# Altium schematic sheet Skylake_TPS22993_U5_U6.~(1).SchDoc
size 431 x 279 mm; Date: Not shown in title block; ApprovedBy: Not shown in title block; CheckedBy: Not shown in title block; Author: Not shown in title block; CompanyName: Not shown in title block; Engineer: Not shown in title block; Organization: Not shown in title block; Address1: Not shown in title block; Address2: Not shown in title block; Address3: Not shown in title block; Address4: Not shown in title block; DocumentNumber: 1; Revision: Use project parameter SCH_Rev; SheetNumber: 3; SheetTotal: 9; PageSetup: Record=PageOptions|CenterHorizontal=True|CenterVertical=True|PrintScale=1.00|XCorrection=1.00|YCorrection=1.00|PrintKind=0|BorderSize=5000000|LeftOffset=0|BottomOffset=0|Orientation=2|PaperLength=1000|PaperWidth=1000|Scale=100|PaperSource=15|PrintQuality=600|MediaType=1|DitherType=10|PaperKind=Letter|PrintScaleMode=1
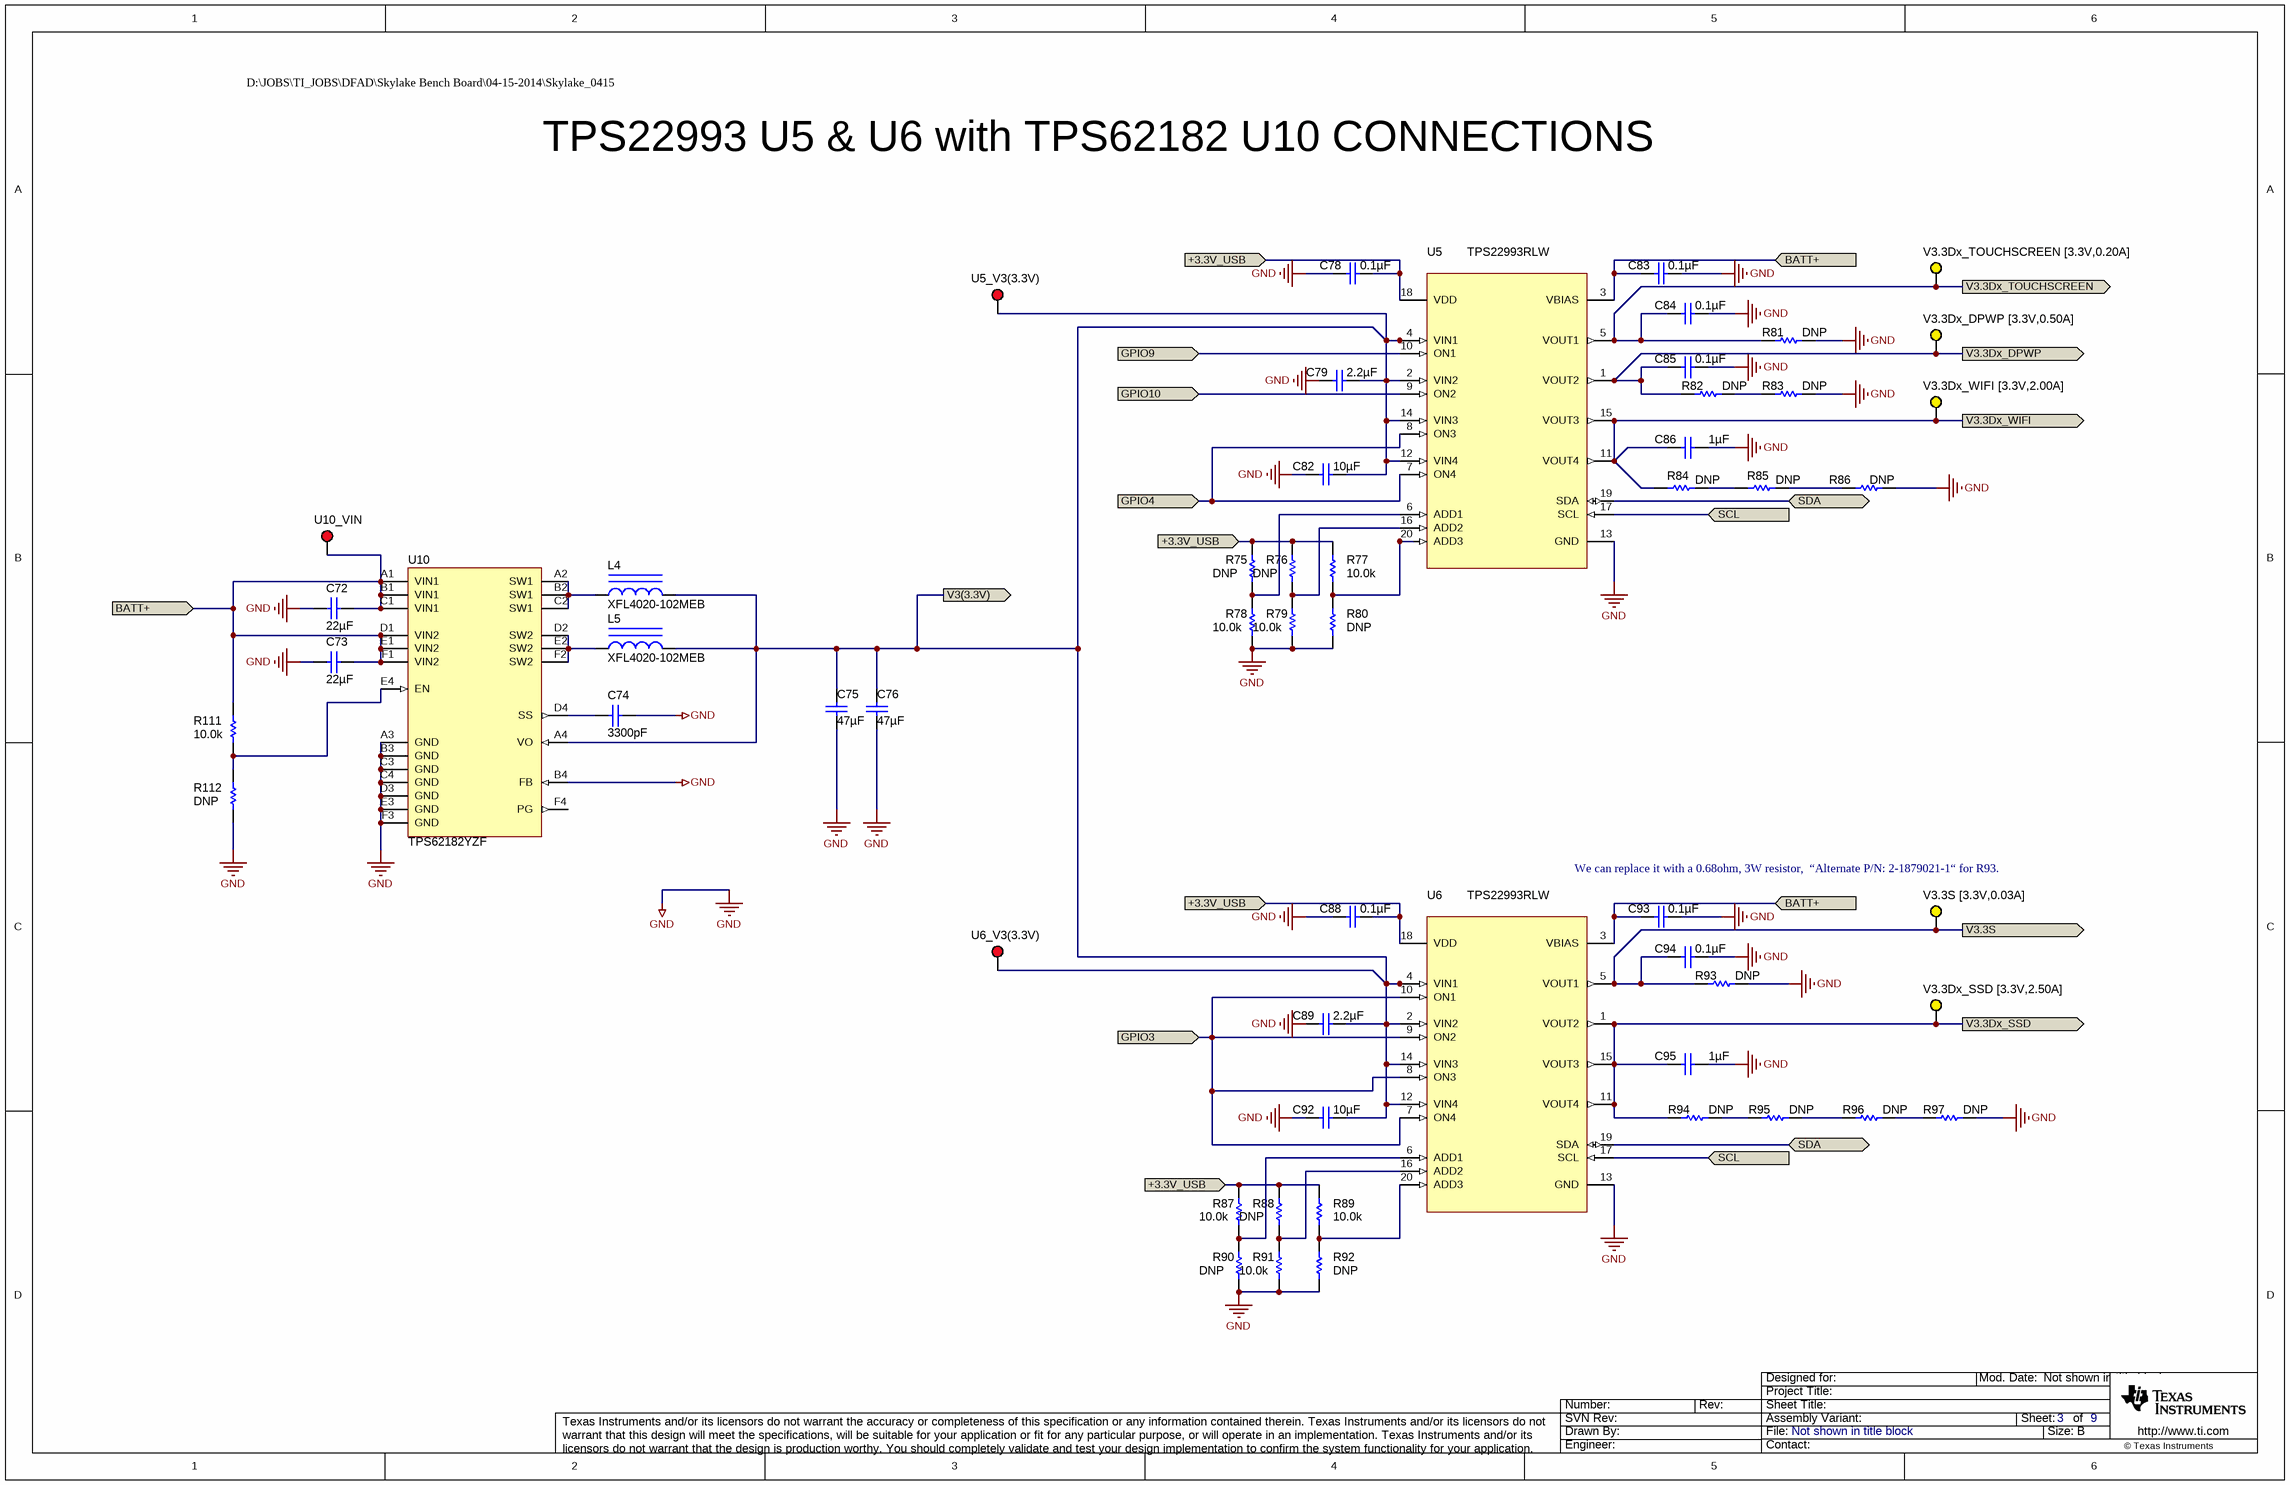
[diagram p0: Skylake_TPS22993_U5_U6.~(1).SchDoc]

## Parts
C72  ValueDisplayed: 22µF  [0805_HV]  (hidden comment: C2012JB1V226M125AC)
C73  ValueDisplayed: 22µF  [0805_HV]  (hidden comment: C2012JB1V226M125AC)
C74  ValueDisplayed: 3300pF  [0603]  (hidden comment: C0603C332J3RACTU)
C75  ValueDisplayed: 47µF  [0805_HV]  (hidden comment: C2012X5R1A476M125AC)
C76  ValueDisplayed: 47µF  [0805_HV]  (hidden comment: C2012X5R1A476M125AC)
C78  ValueDisplayed: 0.1µF  [0603]  (hidden comment: C0603C104K8RACTU)
C79  ValueDisplayed: 2.2µF  [0603]  (hidden comment: GRM188C81A225KE34D)
C82  ValueDisplayed: 10µF  [0805_HV]  (hidden comment: C2012JB1V106K085AC)
C83  ValueDisplayed: 0.1µF  [0805_HV]  (hidden comment: GMK212BJ104KGHT)
C84  ValueDisplayed: 0.1µF  [0603]  (hidden comment: C0603C104K8RACTU)
C85  ValueDisplayed: 0.1µF  [0603]  (hidden comment: C0603C104K8RACTU)
C86  ValueDisplayed: 1µF  [0603]  (hidden comment: C0603C105K8PACTU)
C88  ValueDisplayed: 0.1µF  [0603]  (hidden comment: C0603C104K8RACTU)
C89  ValueDisplayed: 2.2µF  [0603]  (hidden comment: GRM188C81A225KE34D)
C92  ValueDisplayed: 10µF  [0805_HV]  (hidden comment: C2012JB1V106K085AC)
C93  ValueDisplayed: 0.1µF  [0805_HV]  (hidden comment: GMK212BJ104KGHT)
C94  ValueDisplayed: 0.1µF  [0603]  (hidden comment: C0603C104K8RACTU)
C95  ValueDisplayed: 1µF  [0603]  (hidden comment: C0603C105K8PACTU)
L4  XFL4020-102MEB  [XFL4020]
L5  XFL4020-102MEB  [XFL4020]
R75  value DNP  [0402]  (hidden comment: CRCW040210K0FKED)
R76  value DNP  [0402]  (hidden comment: CRCW040210K0FKED)
R77  value 10.0k  [0402]  (hidden comment: CRCW040210K0FKED)
R78  value 10.0k  [0402]  (hidden comment: CRCW040210K0FKED)
R79  value 10.0k  [0402]  (hidden comment: CRCW040210K0FKED)
R80  value DNP  [0402]  (hidden comment: CRCW040210K0FKED)
R81  value DNP  [2512M]  (hidden comment: RMCF2512FT16R5)
R82  value DNP  [2512M]  (hidden comment: CRCW25123R30FKEGHP)
R83  value DNP  [2512M]  (hidden comment: CRCW25123R30FKEGHP)
R84  value DNP  [PWR5322]  (hidden comment: PWR5322WR500JE)
R85  value DNP  [PWR5322]  (hidden comment: PWR5322WR500JE)
R86  value DNP  [SM_3]  (hidden comment: 2-1879021-1)
R87  value 10.0k  [0402]  (hidden comment: CRCW040210K0FKED)
R88  value DNP  [0402]  (hidden comment: CRCW040210K0FKED)
R89  value 10.0k  [0402]  (hidden comment: CRCW040210K0FKED)
R90  value DNP  [0402]  (hidden comment: CRCW040210K0FKED)
R91  value 10.0k  [0402]  (hidden comment: CRCW040210K0FKED)
R92  value DNP  [0402]  (hidden comment: CRCW040210K0FKED)
R93  value DNP  [1206]  (hidden comment: CRCW1206110RJNEA)
R94  value DNP  [SM_3]  (hidden comment: A103634CT)
R95  value DNP  [SM_3]  (hidden comment: A103634CT)
R96  value DNP  [SM_3]  (hidden comment: A103634CT)
R97  value DNP  [SM_3]  (hidden comment: A103634CT)
R111  value 10.0k  [0402]  (hidden comment: CRCW040210K0FKED)
R112  value DNP  [0402]  (hidden comment: CRCW040210K0FKED)
U5  TPS22993RLW  [RLW0020A]
U5_V3(3.3V)  5005  [Keystone5005]  (value not drawn)
U6  TPS22993RLW  [RLW0020A]
U6_V3(3.3V)  5005  [Keystone5005]  (value not drawn)
U10  TPS62182YZF  [YZF0024AMAM]
U10_VIN  5005  [Keystone5005]  (value not drawn)
V3.3Dx_DPWP_[3.3V,0.50A]  5009  [Keystone5009]  (value not drawn)
V3.3Dx_SSD_[3.3V,2.50A]  5009  [Keystone5009]  (value not drawn)
V3.3Dx_TOUCHSCREEN_[3.3V,0.20A]  5009  [Keystone5009]  (value not drawn)
V3.3Dx_WIFI_[3.3V,2.00A]  5009  [Keystone5009]  (value not drawn)
V3.3S_[3.3V,0.03A]  5009  [Keystone5009]  (value not drawn)

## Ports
+3.3V_USB (in), BATT+ (in), GPIO3 (in), GPIO4 (in), GPIO9 (in), GPIO10 (in), SCL (in), SDA (bidir), V3(3.3V) (out), V3.3Dx_DPWP (out), V3.3Dx_SSD (out), V3.3Dx_TOUCHSCREEN (out), V3.3Dx_WIFI (out), V3.3S (out)

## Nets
GND: C72.2 C73.2 C74.1 C75.2 C76.2 C78.2 C79.2 C82.2 C83.1 C84.1 C85.1 C86.1 C88.2 C89.2 C92.2 C93.1 C94.1 C95.1 R78.1 R79.1 R80.1 R81.2 R83.2 R86.2 R90.1 R91.1 R92.1 R93.2 R97.2 R112.1 U5.13(GND) U6.13(GND) U10.A3(GND) U10.B3(GND) U10.B4(FB) U10.C3(GND) U10.C4(GND) U10.D3(GND) U10.E3(GND) U10.F3(GND)
+3.3V_USB: C78.1 C88.1 R75.2 R76.2 R77.2 R87.2 R88.2 R89.2 U5.18(VDD) U6.18(VDD) ; port +3.3V_USB
BATT+: C72.1 C73.1 C83.2 C93.2 R111.2 U5.3(VBIAS) U6.3(VBIAS) U10.A1(VIN1) U10.B1(VIN1) U10.C1(VIN1) U10.D1(VIN2) U10.E1(VIN2) U10.F1(VIN2) U10_VIN.1 ; port BATT+
GPIO3: U6.7(ON4) U6.8(ON3) U6.9(ON2) U6.10(ON1) ; port GPIO3
GPIO4: U5.7(ON4) U5.8(ON3) ; port GPIO4
GPIO9: U5.10(ON1) ; port GPIO9
GPIO10: U5.9(ON2) ; port GPIO10
SCL: U5.17(SCL) U6.17(SCL) ; port SCL
SDA: U5.19(SDA) U6.19(SDA) ; port SDA
V3(3.3V): C75.1 C76.1 C79.1 C82.1 C89.1 C92.1 L4.2 L5.2 U5.2(VIN2) U5.4(VIN1) U5.12(VIN4) U5.14(VIN3) U5_V3(3.3V).1 U6.2(VIN2) U6.4(VIN1) U6.12(VIN4) U6.14(VIN3) U6_V3(3.3V).1 U10.A4(VO) ; port V3(3.3V)
V3.3Dx_DPWP: C85.2 R82.1 U5.1(VOUT2) V3.3Dx_DPWP_[3.3V,0.50A].1 ; port V3.3Dx_DPWP
V3.3Dx_SSD: C95.2 R94.1 U6.1(VOUT2) U6.11(VOUT4) U6.15(VOUT3) V3.3Dx_SSD_[3.3V,2.50A].1 ; port V3.3Dx_SSD
V3.3Dx_TOUCHSCREEN: C84.2 R81.1 U5.5(VOUT1) V3.3Dx_TOUCHSCREEN_[3.3V,0.20A].1 ; port V3.3Dx_TOUCHSCREEN
V3.3Dx_WIFI: C86.2 R84.1 U5.11(VOUT4) U5.15(VOUT3) V3.3Dx_WIFI_[3.3V,2.00A].1 ; port V3.3Dx_WIFI
V3.3S: C94.2 R93.1 U6.5(VOUT1) V3.3S_[3.3V,0.03A].1 ; port V3.3S
NetC74_2: C74.2 U10.D4(SS)
NetL4_1: L4.1 U10.A2(SW1) U10.B2(SW1) U10.C2(SW1)
NetL5_1: L5.1 U10.D2(SW2) U10.E2(SW2) U10.F2(SW2)
NetR75_1: R75.1 R78.2 U5.6(ADD1)
NetR76_1: R76.1 R79.2 U5.16(ADD2)
NetR77_1: R77.1 R80.2 U5.20(ADD3)
NetR82_2: R82.2 R83.1
NetR84_2: R84.2 R85.1
NetR85_2: R85.2 R86.1
NetR87_1: R87.1 R90.2 U6.6(ADD1)
NetR88_1: R88.1 R91.2 U6.16(ADD2)
NetR89_1: R89.1 R92.2 U6.20(ADD3)
NetR94_2: R94.2 R95.1
NetR95_2: R95.2 R96.1
NetR96_2: R96.2 R97.1
NetR111_1: R111.1 R112.2 U10.E4(EN)

Not connected (* = marked no-connect by the designer): U10 F4(PG)

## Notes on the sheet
- D:\JOBS\TI_JOBS\DFAD\Skylake Bench Board\04-15-2014\Skylake_0415
- TPS22993 U5 & U6 with TPS62182 U10 CONNECTIONS
- We can replace it with a 0.68ohm, 3W resistor,  “Alternate P/N: 2-1879021-1“ for R93.

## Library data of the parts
C72 C73 = GRM21BR61E226ME44: CAP, CERM, 22uF, 35V, +/-20%, X5R, 0805; Manufacturer: TDK Corporation; Polarized: N; CompType: Capacitor; U/M: EA; Cap_F: 0.000022; Tolerance_%: 20; Value1: Unknown; VDC_V: 35; TaMin_C: -55; TaMax_C: 85; Cap_Case: 0805
C74 = C0603C332K5RACTU: CAP, CERM, 3300pF, 25V, +/-5%, X7R, 0603; Manufacturer: Kemet; Polarized: N; CompType: Capacitor; U/M: EA; Cap_F: 0.0000000033; Tolerance_%: 5; Value1: Unknown; VDC_V: 25; TaMin_C: -55; TaMax_C: 125
C75 C76 = GRM21BR61E226ME44: CAP, CERM, 47uF, 10V, +/-20%, X5R, 0805; Manufacturer: TDK Corporation; Polarized: N; CompType: Capacitor; U/M: EA; Cap_F: 0.000022; Tolerance_%: 20; Value1: Unknown; VDC_V: 10; TaMin_C: -55; TaMax_C: 85; Cap_Case: 0805
C78 C84 C85 C88 C94 = GRM188R71C104KA01D: CAP, CERM, 0.1uF, 10V, +/-10%, X7R, 0603; Manufacturer: Kemet; Polarized: N; CompType: Capacitor; U/M: EA; Cap_F: 0.0000001; Tolerance_%: 10; Value1: Unknown; TaMin_C: -55; TaMax_C: 125
C79 C89 = GRM188C81A225KE34D: CAP, CERM, 2.2uF, 10V, +/-10%, X6S, 0603; Manufacturer: MuRata; Polarized: N; CompType: Capacitor; U/M: EA; Cap_F: 0.0000022; Tolerance_%: 10; Value1: Unknown; TaMin_C: -55; TaMax_C: 105
C82 C92 = GRM21BR61E226ME44: CAP, CERM, 10uF, 35V, +/-10%, X5R, 0805; Manufacturer: TDK Corporation; Polarized: N; CompType: Capacitor; U/M: EA; Cap_F: 0.000022; Tolerance_%: 20; Value1: Unknown; VDC_V: 35; TaMin_C: -55; TaMax_C: 85; Cap_Case: 0805
C83 C93 = GRM21BR61E226ME44: CAP, CERM, 0.1uF, 35V, +/-20%, X5R, 0805; Manufacturer: Taiyo Yuden; Polarized: N; CompType: Capacitor; U/M: EA; Cap_F: 0.000022; Tolerance_%: 20; Value1: Unknown; VDC_V: 35; TaMin_C: -55; TaMax_C: 85; Cap_Case: 0805
C86 C95 = C0603C105K8PACTU: CAP, CERM, 1uF, 10V, +/-10%, X5R, 0603; Manufacturer: Kemet; Polarized: N; CompType: Capacitor; U/M: EA; Cap_F: 0.000001; Tolerance_%: 10; Value1: Unknown; TaMin_C: -55; TaMax_C: 85
L4 L5 = XFL4020-102MEB: Inductor, Shielded, Composite, 1uH, 5.4A, 0.01 ohm, SMD; Manufacturer: Coilcraft; Ind_H: 1.0E-6; ValueDisplayed: 1µH; Imax_A: 5.4; Irms: 11A @ 40C rise; Isat: 5.4A @ 30% inductance drop; DCR_ohm: 0.01; U/M: EA
R75 R76 R80 R88 R90 R92 R112 = CRCW040210K0FKED: RES, DNP, 1%, 0.063W, 0402; Manufacturer: Vishay-Dale; CompType: Resistor; Res_ohm: 10000; Value_Code: 10k0; Tolerance_%: 1; Power_W: 0.063; VDC_V: 50; TempCo: 100 ppm/C; EIA_Code: E96; U/M: EA
R77-R79 R87 R89 R91 R111 = CRCW040210K0FKED: RES, 10.0k ohm, 1%, 0.063W, 0402; Manufacturer: Vishay-Dale; CompType: Resistor; Res_ohm: 10000; Value_Code: 10k0; Tolerance_%: 1; Power_W: 0.063; VDC_V: 50; TempCo: 100 ppm/C; EIA_Code: E96; U/M: EA
R81 = CSNL2512FT2L00: RES, DNP, 1%, 1W, 2512; Manufacturer: Stackpole Electronics Inc; CompType: Resistor; Res_ohm: 16.5; Tolerance_%: 1; VDC_V: 200; TempCo: 50 ppm/C; U/M: EA
R82 R83 = CRCW25121K10JNEG: RES, DNP, 5%, 1.5W, 2512; Manufacturer: Vishay-Dale; CompType: Resistor; Tolerance_%: 5; Power_W: 1; VDC_V: 500; TempCo: 200 ppm/C; EIA_Code: E24; U/M: EA
R84 R85 = PWR5322WR500JE: RES, DNP, 5%, 3W, 13.5x5.65x5.5mm; Manufacturer: Bourns; CompType: Resistor; Res_ohm: 0.5; Value_Code: R500; Tolerance_%: 5; Power_W: 3; TempCo: 90 ppm/C; U/M: EA
R86 = SMW31R0JT: RES, DNP, 5%, 3W, SM_3, 10.5x5x5.5mm; Manufacturer: TE Connectivity; CompType: Resistor; Res_ohm: 0.68; Tolerance_%: 5; Power_W: 3; VDC_V: 500; TempCo: 200 ppm/C; EIA_Code: E24; U/M: EA
R93 = CRCW1206110RJNEA: RES, DNP, 5%, 0.25W, 1206; Manufacturer: Vishay-Dale; CompType: Resistor; Res_ohm: 110; Value_Code: 110R; Tolerance_%: 5; Power_W: 0.25; VDC_V: 200; TempCo: 200 ppm/C; EIA_Code: E24; U/M: EA
R94-R97 = SMW31R0JT: RES, DNP, 5%, 3W, SM_3, 10.5x5x5.5mm; Manufacturer: TE Connectivity; CompType: Resistor; Res_ohm: 1; Tolerance_%: 5; Power_W: 3; VDC_V: 500; TempCo: 200 ppm/C; EIA_Code: E24; U/M: EA
U5 U6 = TPS22993RLW: Quad Channel Load Switch with GPIO and I2C Control, RLW0020A; Alternate Manufacturer: None; Manufacturer: Texas Instruments; SymbolCreator: a0411947; CompType: IC; U/M: EA
U5_V3(3.3V) U6_V3(3.3V) U10_VIN = 5005: Test Point, Compact, Red, TH; Manufacturer: Keystone; CompType: Test Point Loop; U/M: EA
U10 = TPS62180YZF: 4 - 17V, 6A, 2-Phase Step-Down Converter, YZF0024AMAM; Alternate Manufacturer: None; Manufacturer: Texas Instruments; SymbolCreator: a0799628; CompType: IC; U/M: EA
V3.3Dx_DPWP_[3.3V,0.50A] V3.3Dx_SSD_[3.3V,2.50A] V3.3Dx_TOUCHSCREEN_[3.3V,0.20A] V3.3Dx_WIFI_[3.3V,2.00A] V3.3S_[3.3V,0.03A] = 5009: Test Point, Compact, Yellow, TH; Manufacturer: Keystone; CompType: Test Point Loop; U/M: EA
